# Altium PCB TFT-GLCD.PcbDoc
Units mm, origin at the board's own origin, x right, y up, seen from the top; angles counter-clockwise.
Board outline 98 x 57 mm, 2 copper layers (Top Layer, Bottom Layer), stack 1.571 mm thick; 54 components, 70 nets, 295 pads, 47 vias.
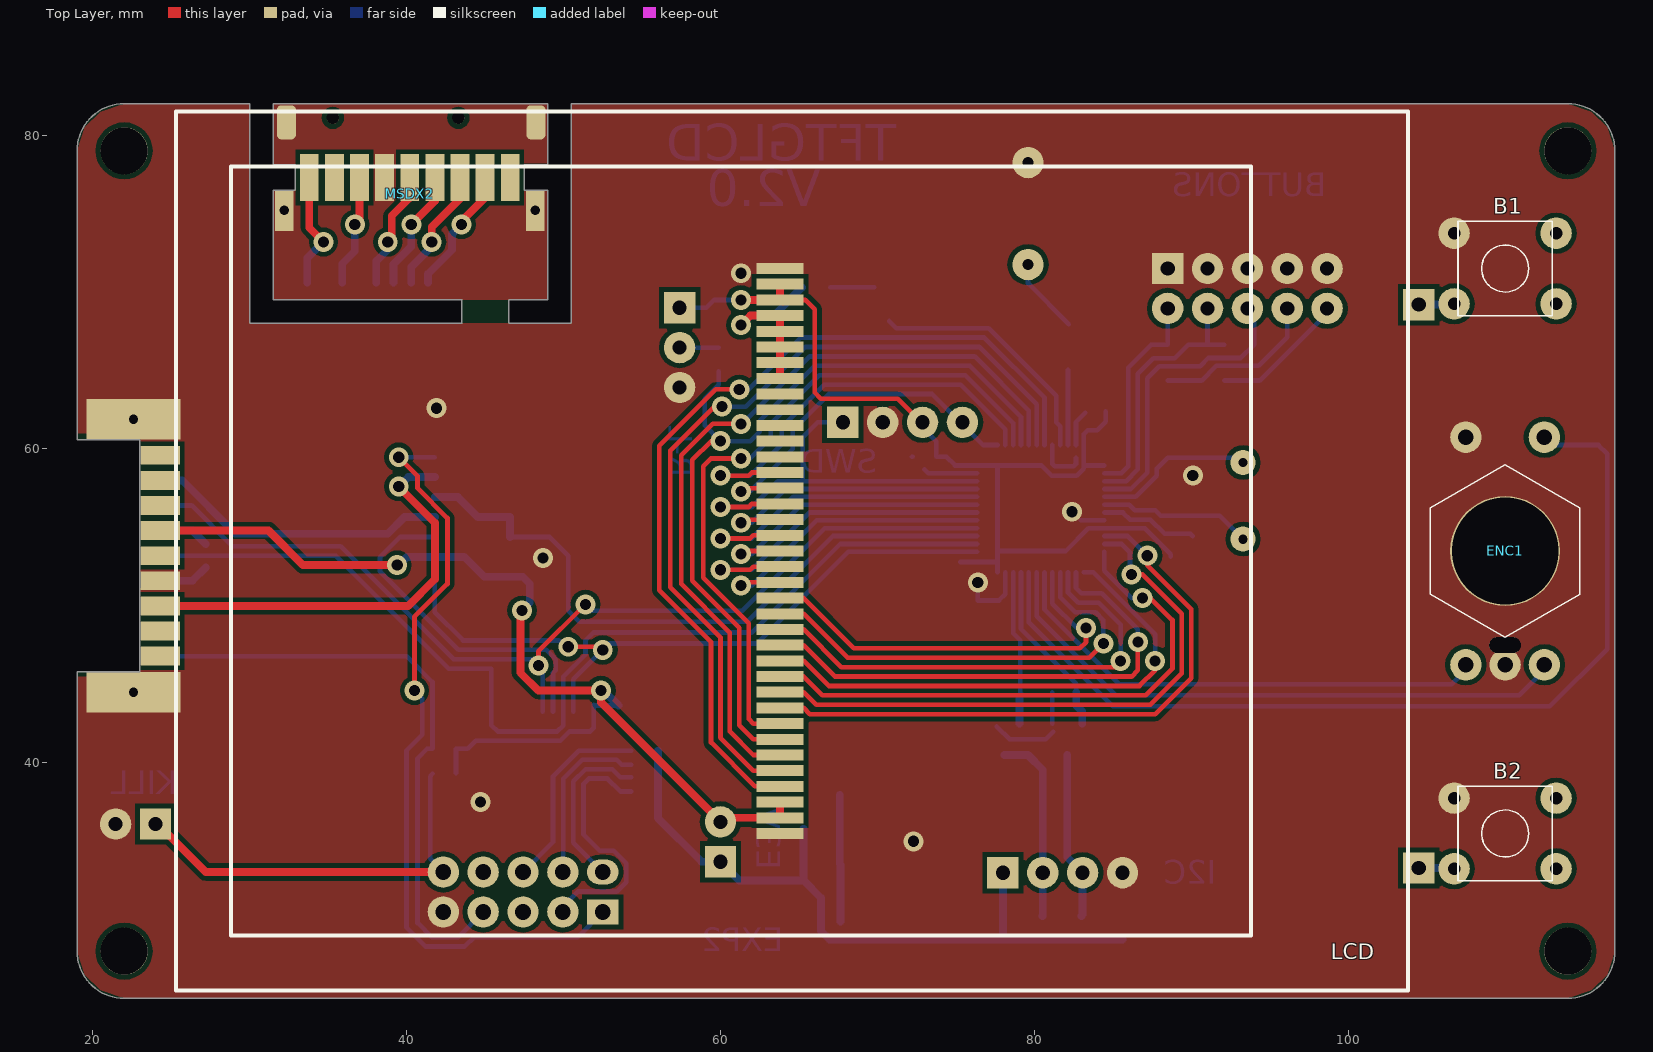
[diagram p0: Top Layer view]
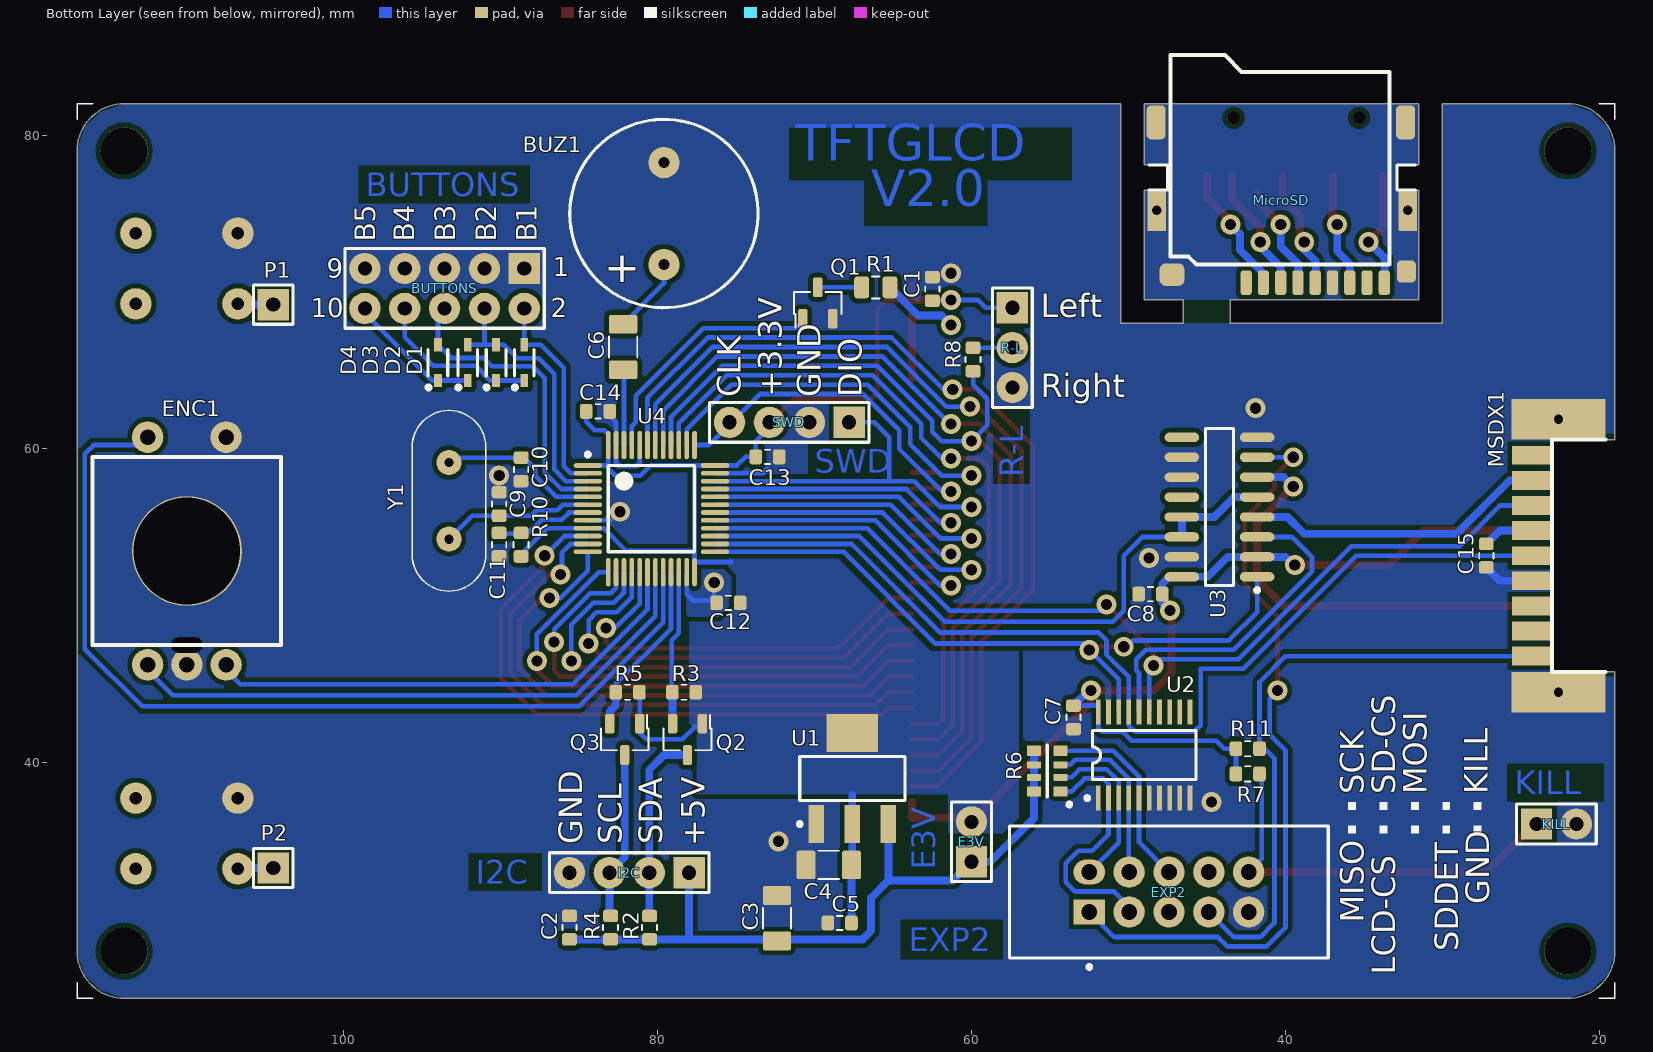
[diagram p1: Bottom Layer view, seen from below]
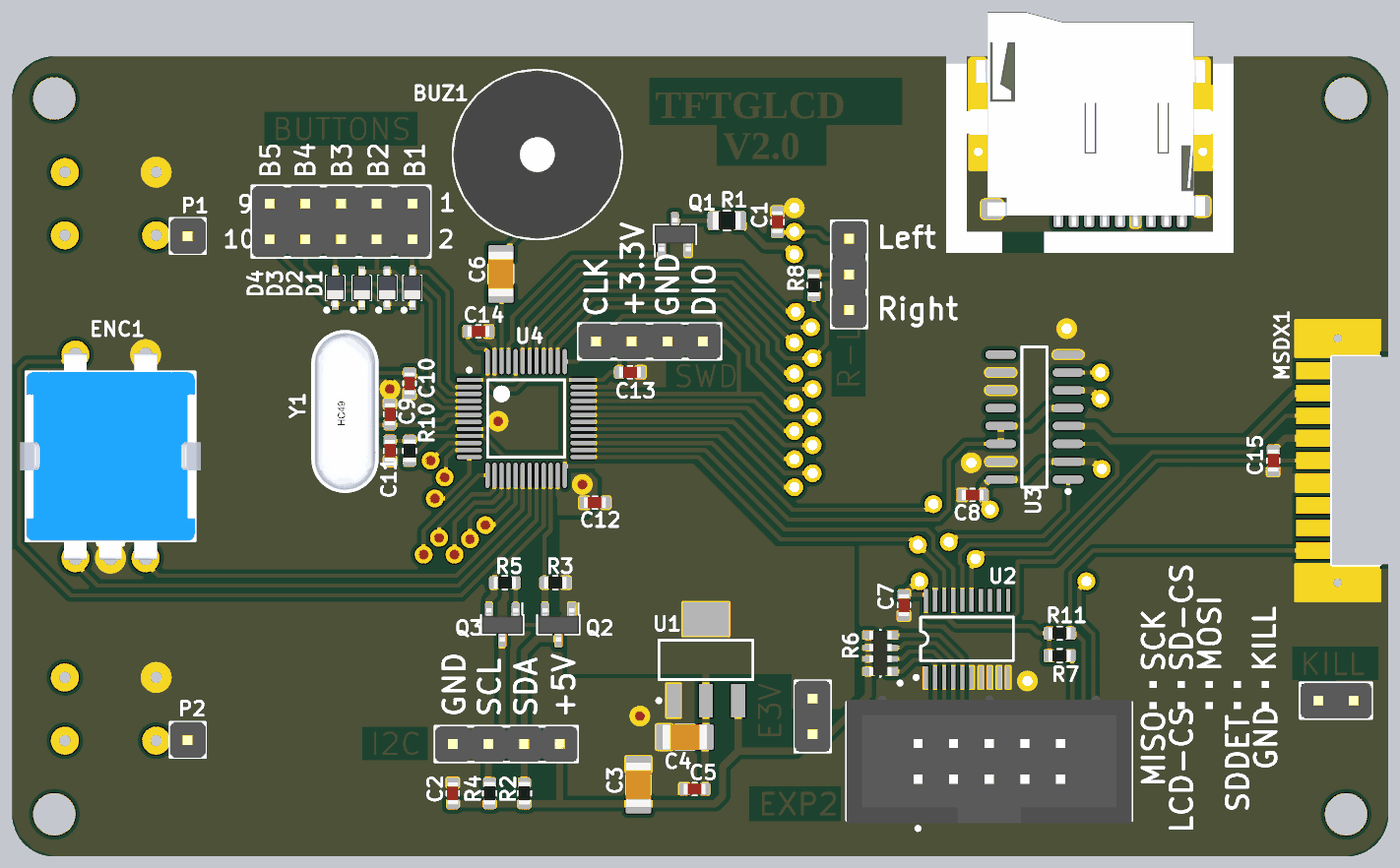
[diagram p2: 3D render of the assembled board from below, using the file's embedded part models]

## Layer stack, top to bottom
Top Solder: solder mask 0.0102, Solder Resist, Dk 3.5
Top Layer: signal copper 0.0356
Dielectric1: core 1.5, FR-4, Dk 4.8
Bottom Layer: signal copper 0.0356
Bottom Solder: solder mask 0.0102, Solder Resist, Dk 3.5

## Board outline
19,28 19,45.8 23,45.8 23,60.6 19,60.6 19,79 cw(c22,79) 22,82 30,82 30,68 43.5,68 43.5,69.5 31.5,69.5 31.5,76.5 32.9,76.5 32.9,78.1 31.5,78.1 31.5,82 49,82 49,78.1 47.5,78.1 47.5,76.5 49,76.5 49,69.5 46.5,69.5 46.5,68 50.5,68 50.5,82 114,82 cw(c114,79) 117,79 117,28 cw(c114,28) 114,25 22,25 cw(c22,28)

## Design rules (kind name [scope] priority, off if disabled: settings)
Clearance Clearance_1 [InPolygon] p1: gap=0.3 ignorepadtopadclearanceinfootprint=FALSE except(0: Arc-Hole Track-Hole SMDPad-Hole THPad-Hole Via-Hole Fill-Hole Poly-Hole Region-Hole Text-Hole)
Clearance [All] p2: gap=0.2 ignorepadtopadclearanceinfootprint=FALSE except(0: Arc-Hole Track-Hole SMDPad-Hole THPad-Hole Via-Hole Fill-Hole Poly-Hole Region-Hole Text-Hole)
ComponentClearance [All] p1 off: gap=0.254 collisioncheckmode=3 verticalgap=0.254 showdistances=FALSE
FabricationTestPointUsage [All] p1 off: valid=0 allowmultiple=FALSE
FabricationTestpoint [All] p1 off: side=3 testpointundercomponent=TRUE minsize=1.016 maxsize=2.54 preferedsize=1.524 minholesize=0 maxholesize=1.016 preferedholesize=0.813 testpointgrid=0.025 allowsidetop=TRUE allowsidebottom=TRUE usegrid=TRUE gridtolerance=0
FanoutControl Fanout_BGA [IsBGA] p1 off: bgadir=Out bgaviamode=Centered fanoutstyle=Auto fanoutdirection=Alternating viagrid=0.025 // Fanout_BGA (Default Rule)
FanoutControl Fanout_LCC [IsLCC] p2 off: bgadir=Out bgaviamode=Centered fanoutstyle=Auto fanoutdirection=Alternating viagrid=0.025 // Fanout_LCC (Default Rule)
FanoutControl Fanout_SOIC [IsSOIC] p3 off: bgadir=Out bgaviamode=Centered fanoutstyle=Auto fanoutdirection=Alternating viagrid=0.025 // Fanout_SOIC (Default Rule)
FanoutControl Fanout_Small [(CompPinCount < 5)] p4 off: bgadir=Out bgaviamode=Centered fanoutstyle=Auto fanoutdirection=OutThenIn viagrid=0.025 // Fanout_Small (Default Rule)
FanoutControl Fanout_Default [All] p5 off: bgadir=Out bgaviamode=Centered fanoutstyle=Auto fanoutdirection=Alternating viagrid=0.025 // Fanout_Default (Default Rule)
PolygonConnect [All] p1: connectstyle=Relief reliefconductorwidth=0.5 reliefentries=4 polygonreliefangle="90 Angle" airgapwidth=-0.1
RoutingVias [All] p1: holewidth=0.711 width=1.27 viastyle="Through Hole" minholewidth=0.711 minwidth=1.27 maxholewidth=0.711 maxwidth=1.27
SilkToSilkClearance [All] p1 off: silktosilkclearance=0.254
SilkToSolderMaskClearance SilkscreenOverComponentPads [IsPad] p1 off: minsilkscreentomaskgap=0.254 clearancetoexposedcopper=TRUE
SolderMaskExpansion [All] p1: expansion=0.1
Width [All] p1: maxlimit=2 minlimit=0.2 preferedwidth=0.3
20 further rules are at their usual default settings.

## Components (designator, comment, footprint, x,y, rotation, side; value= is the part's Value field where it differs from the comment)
B1 "SWT-2-x" SWT-2-x 110,71.5 r0 top
B2 "SWT-2-x" SWT-2-x 110,35.5 r0 top
BUTTONS "Header 5X2" HDR2X5 88.5,71.5 r0 bottom
BUZ1 "Buzer 1205" Buzer_12xx 79.6,75 r90 bottom
C1 "Cap" C0603_Samsung 62.5,70.2 r270 bottom value=100nF
C2 "Cap" C0603_Samsung 85.62,29.5 r270 bottom value=100nF
C3 "Cap" C1206_Murata 72.4,30.1 r270 bottom value=22uF
C4 "Cap" C1206_Murata 69.1,33.5 r180 bottom value=22uF
C5 "Cap" C0603_Samsung 68.4,29.8 r180 bottom value=100nF
C6 "Cap" C1206_Murata 82.2,66.5 r270 bottom value=4.7uF
C7 "Cap" C0603_Samsung 53.5,42.9 r90 bottom value=100nF
C8 "Cap" C0603_Samsung 48.6,50.75 r180 bottom value=100nF
C9 "Cap" C0603_Samsung 90.1,56.5 r270 bottom value=22pF
C10 "Cap" C0603_Samsung 88.7,58.7 r90 bottom value=22pF
C11 "Cap" C0603_Samsung 90.1,53.9 r90 bottom value=100nF
C12 "Cap" C0603_Samsung 75.5,50.2 r180 bottom value=100nF
C13 "Cap" C0603_Samsung 73,59.5 r0 bottom value=100nF
C14 "Cap" C0603_Samsung 83.8,62.4 r0 bottom value=100nF
C15 "Cap" C0603_Samsung 27.2,53.2 r90 bottom value=100nF
D1 "D_Schottky" SOD323FL_NXP 88.5,65.5 r90 bottom
D2 "D_Schottky" SOD323FL_NXP 90.3,65.5 r90 bottom
D3 "D_Schottky" SOD323FL_NXP 92.1,65.5 r90 bottom
D4 "D_Schottky" SOD323FL_NXP 94,65.5 r90 bottom
E3V "Header 2" HDR1X2 60,33.7 r90 bottom
ENC1 "Encoder EC-11" Encoder_bot 110,53.5 r0 top
EXP2 "HEADER 2X5_BH10" BH-10 52.5,30.5 r180 bottom
I2C "Header 4" HDR1X4 78,33 r0 bottom
KILL "Header 2" HDR1X2 24,36.1 r180 bottom
LCD "ILI9325" LCD_ILI9325-37pin 63.8,35.5 r0 top
MicroSD "Micro SD" TFP09-2-12B 42.5,70.6 r180 bottom
MSDX1 "CrossPCB-MicroSD" CrossPCB-MicroSD-MB 24.3,59.6 r270 bottom locked
MSDX2 "CrossPCB-MicroSD" CrossPCB-MicroSD-SD 46.6,77.3 r180 bottom
P1 "Plug" PLS-1x1 104.5,69.2 r180 bottom
P2 "Plug" PLS-1x1 104.5,33.3 r180 bottom
Q1 "IRLML6344" SOT23-3_IR 69.8,69.3 r90 bottom
Q2 "IRLML6344" SOT23-3_IR 78.1,41.5 r270 bottom
Q3 "IRLML6344" SOT23-3_IR 82.1,41.5 r270 bottom
R1 "R" R0805_UniOhm 66.1,70.3 r0 bottom value=33
R2 "R" R0603_UniOhm 80.52,29.5 r270 bottom value=10k
R3 "R" R0603_UniOhm 78.32,44.5 r180 bottom value=10k
R4 "R" R0603_UniOhm 83,29.5 r270 bottom value=10k
R5 "R" R0603_UniOhm 81.92,44.5 r180 bottom value=10k
R6 "array_r_x4s" RES_Array_ROHM_MNR14 55.172,39.476 r0 bottom value=10k
R7 "R" R0603_UniOhm 42.4,39.3 r180 bottom value=10k
R8 "R" R0603_UniOhm 59.9,65.7 r90 bottom value=10k
R10 "R" R0603_UniOhm 88.7,53.9 r90 bottom value=10k
R11 "R" R0603_UniOhm 42.4,40.9 r0 bottom value=10k
R-L "Header 3" HDR1X3 57.4,69 r270 bottom
SWD "Header 4" HDR1X4 67.8,61.7 r0 bottom
U1 "LM1117IMP-3.3" MP04A_N 67.6,39 r90 bottom
U2 "LCX541" TSSOP20 49,40.5 r180 bottom
U3 "74HC157" SO16_N 44.2,56.3 r0 bottom
U4 "STM32F103C8T6" LQFP48_N 80.4,56.2 r180 bottom
Y1 "XTAL" XTAL_HC-49_SS3 93.3,56.7 r90 bottom value=8MHz

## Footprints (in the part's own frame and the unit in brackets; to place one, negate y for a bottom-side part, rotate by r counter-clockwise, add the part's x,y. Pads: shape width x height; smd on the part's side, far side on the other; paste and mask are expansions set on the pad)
BH-10 [mm] "Shrouded Header,vertical,2.54mm pitch;1.00mm lead width,10 pins,2 rows,5 pins per row,20.30mm L X 8.40mm W X 9.30mm H body"
  rect 2x1.6 hole 1: 1(0,0)
  oval 2x1.6 hole 1: 2(0,2.54)
  round 2 hole 1: 3(2.54,0) 4(2.54,2.54) 5(5.08,0) 6(5.08,2.54) 7(7.62,0) 8(7.62,2.54) 9(10.16,0) 10(10.16,2.54)
  silkscreen extent -5.07,-3.63 15.23,5.47, body extent -5.07,-3.13 15.23,5.97, height 9.3
Buzer_12xx [mm]
  round 2 hole 0.7: 1(-3.25,0) 2(3.25,0)
  silkscreen extent -6,-6 6,6, body extent -5.95,-5.99 6,5.99, height 9.5
C0603_Samsung [mm] "Capacitor, Chip; 1.60 mm L X 0.80 mm W X 0.90 mm H body"
  rrect40% 0.8x0.95 smd paste-0.025 mask+0.05: 1(-0.75,0) 2(0.75,0)
  silkscreen extent -0.17,-0.45 0.17,0.45, body extent -0.8,-0.4 0.8,0.4, height 0.9
C1206_Murata [mm] "Capacitor, Chip; 3.20 mm L X 1.60 mm W X 1.80 mm H body"
  rrect20% 1.2x1.8 smd: 1(-1.45,0) 2(1.45,0)
  silkscreen extent -0.67,-0.9 0.67,0.9, body extent -1.6,-0.9 1.6,0.9, height 1.6
CrossPCB-MicroSD-MB [mm] "MicroSD CrossPCB connector MB side"
  rect 1.2x2.5 all layers, no hole: 1(0,0) 2(1.6,0) 3(3.2,0) 4(4.8,0) 5(6.4,0) 6(8,0) 7(9.6,0) 8(11.2,0) 9(12.8,0)
  rect 2.6x6 hole 0.6: 10(-2.3,1.7) 10(15.1,1.7)
  silkscreen extent -1,1.3 13.8,4.7
CrossPCB-MicroSD-SD [mm] "MicroSD CrossPCB connector SD side"
  rect 1.2x3 smd far side: 1(0,0) 2(1.6,0) 3(3.2,0) 4(4.8,0) 5(6.4,0) 6(8,0) 7(9.6,0) 8(11.2,0) 9(12.8,0)
  rect 1.2x2.6 hole 0.6: 10(-1.6,-2.1) 10(14.4,-2.1)
  silkscreen extent -2.1,-0.8 14.9,0.8
Encoder_bot [mm]
  oval 2x1 hole 1 slot 2 at 0 deg: 0(0,-6)
  round 7 hole 6.8: 0(0,0)
  round 2 hole 1: 1(-2.5,-7.25) 2(0,-7.25) 3(2.5,-7.25) 4(-2.5,7.25) 5(2.5,7.25)
  silkscreen extent -4.76,-5.5 4.76,5.5, body extent -6.43,-7.35 6.43,7.35, height 13.5
HDR1X2 [mm] "Connector; Header; 2 Position"
  rect 2x2 hole 0.9: 1(0,0)
  round 2 hole 0.9: 2(2.54,0)
  silkscreen extent -1.27,-1.27 3.81,1.27, body extent -1.25,-1.27 3.83,1.27, height 9
HDR1X3 [mm] "Connector; Header; 3 Position"
  rect 2x2 hole 0.9: 1(0,0)
  round 2 hole 0.9: 2(2.54,0) 3(5.08,0)
  silkscreen extent -1.27,-1.27 6.35,1.27, body extent -1.27,-1.27 6.35,1.27, height 9
HDR1X4 [mm] "Connector; Header; 4 Position"
  rect 2x2 hole 0.9: 1(0,0)
  round 2 hole 0.9: 2(2.54,0) 3(5.08,0) 4(7.62,0)
  silkscreen extent -1.27,-1.27 8.89,1.27, body extent -1.27,-1.27 8.89,1.27, height 9
HDR2X5 [mm] "Connector; Header; 5x2 Position"
  rect 2x2 hole 0.9: 1(0,0)
  round 2 hole 0.9: 2(0,2.54) 3(2.54,0) 4(2.54,2.54) 5(5.08,0) 6(5.08,2.54) 7(7.62,0) 8(7.62,2.54) 9(10.16,0) 10(10.16,2.54)
  silkscreen extent -1.27,-1.27 11.43,3.81, body extent -1.27,-1.27 11.43,3.81, height 9
LCD_ILI9325-37pin [mm]
  rect 3x0.7 smd: 1(0,0) 2(0,1) 3(0,2) 4(0,3) 5(0,4) 6(0,5) 7(0,6) 8(0,7) 9(0,8) 10(0,9) 11(0,10) 12(0,11) 13(0,12) 14(0,13) 15(0,14) 16(0,15) 17(0,16) 18(0,17) 19(0,18) 20(0,19) 21(0,20) 22(0,21) 23(0,22) 24(0,23) 25(0,24) 26(0,25) 27(0,26) 28(0,27) 29(0,28) 30(0,29) 31(0,30) 32(0,31) 33(0,32) 34(0,33) 35(0,34) 36(0,35) 37(0,36)
  silkscreen extent -38.5,-10 40,46, body extent -38.5,-10 40.1,46, height 3
LQFP48_N [mm] "Thin QFP, 48-Leads, Body 7x7mm, Pitch 0.5mm, IPC Medium Density"
  oval 1.8x0.3 smd: 1(-4.05,2.75) 2(-4.05,2.25) 3(-4.05,1.75) 4(-4.05,1.25) 5(-4.05,0.75) 6(-4.05,0.25) 7(-4.05,-0.25) 8(-4.05,-0.75) 9(-4.05,-1.25) 10(-4.05,-1.75) 11(-4.05,-2.25) 12(-4.05,-2.75) 25(4.05,-2.75) 26(4.05,-2.25) 27(4.05,-1.75) 28(4.05,-1.25) 29(4.05,-0.75) 30(4.05,-0.25) 31(4.05,0.25) 32(4.05,0.75) 33(4.05,1.25) 34(4.05,1.75) 35(4.05,2.25) 36(4.05,2.75)
  oval 0.3x1.8 smd: 13(-2.75,-4.05) 14(-2.25,-4.05) 15(-1.75,-4.05) 16(-1.25,-4.05) 17(-0.75,-4.05) 18(-0.25,-4.05) 19(0.25,-4.05) 20(0.75,-4.05) 21(1.25,-4.05) 22(1.75,-4.05) 23(2.25,-4.05) 24(2.75,-4.05) 37(2.75,4.05) 38(2.25,4.05) 39(1.75,4.05) 40(1.25,4.05) 41(0.75,4.05) 42(0.25,4.05) 43(-0.25,4.05) 44(-0.75,4.05) 45(-1.25,4.05) 46(-1.75,4.05) 47(-2.25,4.05) 48(-2.75,4.05)
  silkscreen extent -4.18,-2.75 2.75,3.57, body extent -3.5,-3.5 3.5,3.5, height 1.6
MP04A_N [mm] "SOT223, 4-Leads, Body 6.5x3.5mm, Pitch 2.3mm, Lead Span 7mm, IPC Medium Density"
  rect 2.4x1 smd: 1(-2.9,2.3) 2(-2.9,0) 3(-2.9,-2.3)
  rect 2.4x3.3 smd: 4(2.9,0)
  silkscreen extent -3.02,-3.35 1.4,3.48, body extent -1.85,-3.35 1.85,3.35, height 1.8
PLS-1x1 [mm]
  rect 2x2 hole 0.9: 1(0,0)
  silkscreen extent -1.25,-1.25 1.25,1.25, body extent -1.27,-1.27 1.27,1.27, height 9
R0603_UniOhm [mm] "Resistor, Chip; 1.60 mm L X 0.825 mm W X 0.55 mm H body"
  rrect40% 0.8x0.95 smd paste-0.025 mask+0.05: 1(-0.75,0) 2(0.75,0)
  silkscreen extent -0.17,-0.48 0.17,0.48, body extent -0.8,-0.41 0.8,0.41, height 0.55
R0805_UniOhm [mm] "Resistor, Chip; 2.00 mm L X 1.275 mm W X 0.65 mm H body"
  rrect40% 0.95x1.4 smd paste-0.025 mask+0.05: 1(-0.9,0) 2(0.9,0)
  silkscreen extent -0.25,-0.7 0.25,0.7, body extent -1,-0.64 1,0.64, height 0.65
RES_Array_ROHM_MNR14 [mm] "Resistor,Chip Array,0.80mm pitch;8 pin,1.60mm W X 3.20mm L X 0.60mm H, Convex"
  rrect15% 0.9x0.65 smd paste-0.025 mask+0.05: 1(-0.85,1.3) 4(-0.85,-1.3) 5(0.85,-1.3) 8(0.85,1.3)
  rrect22% 0.9x0.45 smd paste-0.025 mask+0.05: 2(-0.85,0.4) 3(-0.85,-0.4) 6(0.85,-0.4) 7(0.85,0.4)
  silkscreen extent -1.52,-1.65 0,2.25, body extent -0.8,-1.6 0.8,1.6, height 0.55
SO16_N [mm] "SOIC, 16-Leads, Body 9.9x3.9mm, Pitch 1.27mm, IPC Medium Density"
  oval 2.2x0.6 smd: 1(-2.4,4.445) 2(-2.4,3.175) 3(-2.4,1.905) 4(-2.4,0.635) 5(-2.4,-0.635) 6(-2.4,-1.905) 7(-2.4,-3.175) 8(-2.4,-4.445) 9(2.4,-4.445) 10(2.4,-3.175) 11(2.4,-1.905) 12(2.4,-0.635) 13(2.4,0.635) 14(2.4,1.905) 15(2.4,3.175) 16(2.4,4.445)
  silkscreen extent -2.52,-5 0.9,5.42, body extent -1.95,-4.95 1.95,4.95, height 1.75
SOD323FL_NXP [mm] "SODFL Diode;1.80mm W X 1.35mm L X 0.80mm H body"
  rrect10% 0.85x0.5 smd paste-0.025 mask+0.05: A(1.14,0) C(-1.14,0)
  silkscreen extent -1.7,-0.63 0.85,0.73, body extent -1.35,-0.67 1.35,0.68, height 0.79
SOT23-3_IR [mm] "Small Outline Transistor (SOT23), 0.95 mm pitch; 3 pin, 2.92 mm L X 1.30 mm W X 1.12 mm H body"
  rrect40% 1.25x0.6 smd paste-0.025 mask+0.05: 1(-1,0.95) 2(-1,-0.95) 3(1,0)
  silkscreen extent -1.57,-1.52 0.7,1.52, body extent -1.18,-1.46 1.18,1.46, height 1.12
SWT-2-x [mm] "Button"
  round 2 hole 0.8: 1(-3.25,2.25) 2(-3.25,-2.25) 3(3.25,-2.25) 4(3.25,2.25)
  silkscreen extent -3,-3 3,3
TFP09-2-12B [mil] "http://ali.pub/2rgdx8"
  round 30 hole 31.5 mask+0: 0(-31.5,413.39) 0(283.46,413.39)
  rrect50% 28x62 smd: 1(0,0) 2(43.31,0) 3(86.61,0) 4(129.92,0) 5(173.23,0) 6(216.54,0) 7(259.84,0) 8(303.15,0) 9(346.46,0)
  rrect50% 48x56 smd: 10(402,28)
  rrect50% 62x56 smd: 11(-186,20)
  rrect50% 48x86 all layers, no hole: 12(-226,402) 12(400,402)
  silkscreen extent -190,45 360,571, body extent -230,-27 412,572, height 79
TSSOP20 [mm] "Shrink Small Outline; 20 Leads; Body Width 4.4 mm; Pitch 0.65 mm"
  rect 0.3x1.6 smd: 1(-2.925,-2.75) 2(-2.275,-2.75) 3(-1.625,-2.75) 4(-0.975,-2.75) 5(-0.325,-2.75) 6(0.325,-2.75) 7(0.975,-2.75) 8(1.625,-2.75) 9(2.275,-2.75) 10(2.925,-2.75) 11(2.925,2.75) 12(2.275,2.75) 13(1.625,2.75) 14(0.975,2.75) 15(0.325,2.75) 16(-0.325,2.75) 17(-0.975,2.75) 18(-1.625,2.75) 19(-2.275,2.75) 20(-2.925,2.75)
  silkscreen extent -3.75,-2.87 3.3,1.55
XTAL_HC-49_SS3 [mm] "Quartz"
  round 1.6 hole 0.6: 1(-2.438,0) 2(2.438,0)
  silkscreen extent -5.76,-2.35 5.76,2.35, body extent -5.75,-2.32 5.75,2.33, height 3.5

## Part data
BUTTONS: "Header, 5-Pin, Dual row"
BUZ1: library part Buzer
C1 C2 C5 C7 C8 C11 C12 C13 C14 C15: library part CL10B104KB8NNNC, Manufacturer="Samsung Electro-Mechanics", PartName=CL10, Tolerance="10 %", Voltage=50V
C3 C4 C6: library part GRM31CR71H475KA12L, Manufacturer=muRata, PartName=GRM31, Tolerance="10 %", Voltage=50V
C9 C10: library part CL10C220JB8NNNC, Manufacturer="Samsung Electro-Mechanics", PartName=CL10, Tolerance="5 %", Voltage=50V
D1 D2 D3 D4: library part PMEG6010CEJ,115, "60V, 1A, very low VF MEGA Schottky barrier rectifiers", Manufacturer="NXP Semiconductors", PartName=PMEG6010CEJ
E3V KILL: "Header, 2-Pin"
ENC1: library part Encoder, "Rotary Encoder with button"
EXP2: library part BH-10, "IDC-10M Connector (BH-10)", Manufacturer=Unknown, PartName=BH-10V
I2C SWD: "Header, 4-Pin"
LCD: library part LCD_ILI9325-37pin
MicroSD: library part TFP09-2-12B
MSDX1 MSDX2: "Micro SD CrossPCB connector"
Q1 Q2 Q3: library part IRLML6344TRPBF, "30 V, 5.0 A, 0.029 Ohm Single N-Channel HEXFET Power MOSFET", Manufacturer="International Rectifier"
R1: library part 0805S8F4700T50, Manufacturer=uniOhm, PartName=0805S, TempCo="100 ppm", Tolerance="1 %"
R2 R3 R4 R5 R7 R8 R10 R11: library part 0603SAF1002T50, Manufacturer=uniOhm, PartName=0603SA, TempCo="100 ppm", Tolerance="1 %"
R6: library part MNR14ERAPJ103, "4x Chip Array Convex", Manufacturer=ROHM, PartName=MNR14, TempCo="200 ppm", Tolerance="5 %"
R-L: "Header, 3-Pin"
U1: "800mA Low-Dropout Linear Regulator", DigiKeyPartNumber=LM1117IMP-3.3CT-ND, Manufacturer="National Semiconductor", PackageTopMarking=XYTT*N05B, PowerWise=N
U2: library part 74LCX541MTC, "Low Voltage Octal Buffer with 5V Tolerant Inputs and Outputs", Manufacturer="Fairchild Semiconductor", PartName=LVC541PW
U3: library part 74LVQ157M, "Low-Voltage Quad 2-Channel Multiplexer"
U4: "STM32 ARM-based 32-bit MCU with 64 Kbytes Flash, 48-pin LQFP, Industrial Temperature"
Y1: library part "KX-3HT 10.0MHZ", "10MHz Quartz HC49", Manufacturer="GEYER ELECTRONIC", PartName=KX-3HT

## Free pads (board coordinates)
  round 3 hole 3: 1(22,28) 1(22,79) 1(114,28) 1(114,79)

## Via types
v1: diameter 1.27, hole 0.711, Top Layer to Bottom Layer, 47 vias

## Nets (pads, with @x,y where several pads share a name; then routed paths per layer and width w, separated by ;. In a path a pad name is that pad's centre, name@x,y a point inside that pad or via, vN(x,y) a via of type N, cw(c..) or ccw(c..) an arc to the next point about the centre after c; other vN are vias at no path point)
+3.3V: C1.2 C4.2 C5.2 C7.2 C8.2 C12.2 C13.2 C14.2 C15.2 E3V.2 LCD.2 LCD.3 LCD.35 LCD.36 MSDX1.4 Q2.1 Q3.1 R3.2 R5.2 R7.1 R10.1 R11.2 R-L.1 SWD.3 U1.2 U1.4 U2.20 U3.2 U3.16 U4.1 U4.9 U4.24 U4.36 U4.48 | length 150.6
  Top Layer w0.3: LCD.35@64,69.3 64.2,69.5 65.4,69.5 66,68.9 66,63.6 66.4,63.2 71.3,63.2 SWD.3@72.79,61.71
  Top Layer w0.5: MSDX1.4 31.2,54.8 33.4,52.6 v1(39.4,52.6) ; v1(47.359,49.716) 47.25,49.607 47.25,45.75 48.4,44.6 v1(52.384,44.6) 52.384,43.856 E3V.2 60.26,36.5 LCD.2 LCD.3 ; v1(61.3,69.5) LCD.35 LCD.36
  Bottom Layer w0.3: R7.1@43.15,39.35 R11.2 43.9,40.9 44.4,41.4 49.8,41.4 50.4,42 51.7,42 51.925,42.225 U2.20 51.925,43.7 51.975,43.65 C7.2 ; R-L.1 59.1,69 59.6,69.5 v1(61.3,69.5) ; v1@61.25,69.45 C1.2 C1.2@62.45,69.4 ; SWD.3@72.54,61.7 73.75,60.49 C13.2 74.4,59.5 74.95,58.95 U4.36 77.65,58.95 ; 75.3,52.8 U4.24@77.65,52.8 ; 77.61,42.31 78.42,41.5 80.72,41.5 Q3.1@81.2,41.98 ; U4.24 U4.24@77.65,52.8 ; Q3.1 R5.2@81.15,44.48 ; U4.1 83.15,58.95 ; C14.2 84.55,61.75 84,61.2 83.4,61.2 83.15,60.95 U4.48 83.15,58.95 ; R10.1 88.7,53.3 87.05,54.95 U4.9 83.45,54.95 82,53.5 77.65,53.5 ; U4.24@77.65,52.8 77.65,53.5 ; 77.65,53.5 77.65,58.95 ; 77.65,58.95 80.45,58.95 81.1,58.3 82.7,58.3 83.15,58.75 83.15,58.95
  Bottom Layer w0.5: MSDX1.4 26.35,54.8 C15.2 ; v1(39.4,52.6) 39.5,52.6 40.025,53.125 U3.2 43.675,53.125 44.945,51.855 U3.16 47.4,51.855 47.85,51.405 C8.2 47.85,50.207 v1(47.359,49.716) ; v1(52.384,44.6) 52.55,44.6 C7.2 ; C4.2@67.6,33.55 U1.2 67.6,37.95 ; C5.2@67.65,29.9 C4.2
+5V: C2.2 C3.2 E3V.1 I2C.1 R2.2 R4.2 R6.5 R6.6 R6.7 R6.8 U1.3 | length 45.9
  Bottom Layer w0.5: R6.5 R6.6 R6.7 R6.8 56.022,36.478 58.8,33.7 E3V.1 61.2,32.5 65.3,32.5 ; U1.3@65.3,35.8 65.3,32.5 ; I2C.1 78,28.75 ; C2.2 R2.2 78,28.75 ; 65.3,32.5 66.4,31.4 66.4,29.3 66.95,28.75 78,28.75
B1: BUTTONS.2 D1.A U4.2 | length 13.5
  Bottom Layer w0.3: U4.2 85.55,58.45 85.99,58.89 85.99,65.19 87.44,66.64 D1.A BUTTONS.2
B2: BUTTONS.4 D2.A D3.A U4.3 | length 17.1
  Bottom Layer w0.3: U4.3 85.85,57.95 86.6,58.7 86.6,64.8 87.576,65.776 88.957,65.776 89.821,66.64 D2.A D3.A ; 91.04,66.68 BUTTONS.4
B3: BUTTONS.6 D4.A U4.4 | length 19.4
  Bottom Layer w0.3: U4.4 86.15,57.45 87.2,58.5 87.2,64.5 87.976,65.276 90.576,65.276 91.1,65.8 93.16,65.8 D4.A 94,68.54 BUTTONS.6
B4: BUTTONS.8 D1.C D2.C | length 10.6
  Bottom Layer w0.3: D1.C D2.C 90.66,64.36 91.6,65.3 94.3,65.3 96.12,67.12 BUTTONS.8
B5: BUTTONS.10 D3.C D4.C | length 8.3
  Bottom Layer w0.3: D3.C D4.C 94.36,64.36 BUTTONS.10@98.66,68.66
BEEP: C6.2 U4.46 | length 4.8
  Bottom Layer w0.3: U4.46 C6.2@82.15,65.05
BRIGHTNES: Q1.1 U4.45 | length 15.9
  Bottom Layer w0.3: Q1.1@70.75,68.15 71.2,67.7 77.1,67.7 81.4,63.4 81.4,61.7 81.65,61.45 U4.45
BTNEN2: EXP2.5
CS-: LCD.4 U4.43 | length 57.8
  Top Layer w0.3: v1(61.2,63.8) 59.7,63.8 56.1,60.2 56.1,51 59.4,47.7 59.4,41.3 62.2,38.5 LCD.4
  Bottom Layer w0.3: v1(61.2,63.8) 61.8,63.8 65.1,67.1 76.8,67.1 80.65,63.25 U4.43
CS-LCD: U2.18 U3.1 U4.25 | length 45.2
  Top Layer w0.3: v1(50.3,47.4) 52.3,47.4 v1(52.5,47.2)
  Bottom Layer w0.3: U3.1 41.8,49.6 43.6,47.8 49.7,47.8 50.1,47.4 v1@50.149,47.4 ; v1@50.1,47.449 v1@50.149,47.4 ; v1(50.3,47.4) v1@50.149,47.4 ; U2.18 50.625,45.325 v1(52.5,47.2) 52.9,47.6 62.3,47.6 68.15,53.45 U4.25
CS-SD: MSDX1.2 U3.4 | length 19.3
  Bottom Layer w0.5: MSDX1.2 25.7,58 29.1,54.6 38.8,54.6 39.865,55.665 U3.4
CS-SD-I: U2.16 U3.3 | length 21.9
  Bottom Layer w0.3: U3.3 39.595,54.395 38.3,53.1 38.3,52.2 43.3,47.2 48.9,47.2 49.5,46.6 49.5,45.9 49.325,45.725 U2.16
D0: LCD.9 U4.10 | length 39.9
  Top Layer w0.3: LCD.9 65.3,43.5 65.7,43.1 87.7,43.1 90,45.4 90,49.8 87.2,52.6 v1(87.2,53.2)
  Bottom Layer w0.3: U4.10 85.95,54.45 v1(87.2,53.2) v1@87.45,52.95
D1: LCD.10 U4.11 | length 38.2
  Top Layer w0.3: LCD.10 65.3,44.5 66.1,43.7 87.4,43.7 89.4,45.7 89.4,49.5 86.9,52 v1(86.2,52) v1@86.1,52
  Bottom Layer w0.3: U4.11 85.55,53.95 86.1,53.4 v1@86.1,52
D2: LCD.11 U4.12 | length 36.2
  Top Layer w0.3: LCD.11 65.3,45.5 66.5,44.3 87.1,44.3 88.8,46 88.8,49.1 87.4,50.5 v1(86.9,50.5)
  Bottom Layer w0.3: U4.12 84.45,52.25 86.2,50.5 v1(86.9,50.5)
D3: LCD.12 U4.13 | length 33.5
  Top Layer w0.3: LCD.12 65.3,46.5 66.9,44.9 86.7,44.9 87.7,45.9 v1(87.7,46.5)
  Bottom Layer w0.3: U4.13 83.75,52.15 87.7,48.2 v1(87.7,46.5)
D4: LCD.13 U4.14 | length 32.4
  Top Layer w0.3: LCD.13 65.3,47.5 67.3,45.5 86.2,45.5 86.6,45.9 v1(86.6,47.7)
  Bottom Layer w0.3: U4.14 82.65,51.15 83,50.8 84.3,50.8 86.6,48.5 v1(86.6,47.7)
D5: LCD.14 U4.15 | length 30.7
  Top Layer w0.3: LCD.14 65.3,48.5 67.7,46.1 85.1,46.1 v1(85.5,46.5)
  Bottom Layer w0.3: U4.15 82.15,50.85 82.8,50.2 84.1,50.2 85.5,48.8 v1(85.5,46.5)
D6: LCD.15 U4.16 | length 28.6
  Top Layer w0.3: LCD.15 65.3,49.5 68.1,46.7 83.5,46.7 v1(84.4,47.6)
  Bottom Layer w0.3: U4.16 81.65,50.55 82.6,49.6 83.9,49.6 84.4,49.1 v1(84.4,47.6)
D7: LCD.16 U4.17 | length 27.1
  Top Layer w0.3: LCD.16 65.3,50.5 68.5,47.3 82.9,47.3 83.3,47.7 v1(83.3,48.6)
  Bottom Layer w0.3: U4.17 81.15,50.15 82.7,48.6 v1(83.3,48.6) ; v1@83.4,48.7 v1@83.7,48.4
D8: LCD.17 U4.29 | length 19.4
  Top Layer w0.3: v1(61.3,51.3) 61.5,51.5 LCD.17
  Bottom Layer w0.3: v1(61.3,51.3) 62,51.3 66.15,55.45 U4.29
D9: LCD.18 U4.30 | length 21.7
  Top Layer w0.3: v1(60,52.3) 61.9,52.3 62.1,52.5 LCD.18
  Bottom Layer w0.3: v1(60,52.3) 62,52.3 65.65,55.95 U4.30
D10: LCD.19 U4.31 | length 18.9
  Top Layer w0.3: v1(61.3,53.3) 61.5,53.5 LCD.19
  Bottom Layer w0.3: v1(61.3,53.3) 62,53.3 65.15,56.45 U4.31
D11: LCD.20 U4.32 | length 21.3
  Top Layer w0.3: v1(60,54.3) 61.9,54.3 62.1,54.5 LCD.20
  Bottom Layer w0.3: v1(60,54.3) 62,54.3 64.65,56.95 U4.32
D12: LCD.21 U4.33 | length 18.5
  Top Layer w0.3: v1(61.3,55.3) 61.5,55.5 LCD.21
  Bottom Layer w0.3: v1(61.3,55.3) 62,55.3 64.15,57.45 U4.33
D13: LCD.22 SWD.1 U4.34 | length 26.3
  Top Layer w0.3: v1(60,56.3) 61.8,56.3 62,56.5 LCD.22
  Bottom Layer w0.3: v1(60,56.3) 62,56.3 63.65,57.95 65.25,57.95 ; SWD.1@67.46,61.7 66.2,61.7 65.25,60.75 65.25,57.95 ; U4.34 65.25,57.95
D14: LCD.23 SWD.4 U4.37 | length 23.6
  Top Layer w0.3: v1(61.3,57.3) 61.5,57.5 LCD.23
  Bottom Layer w0.3: v1(61.3,57.3) 61.9,57.3 64.6,60 64.6,61.2 66.9,63.5 73.5,63.5 76.75,60.25 U4.37
D15: LCD.24 U4.38 | length 27.3
  Top Layer w0.3: v1(60,58.3) 61.8,58.3 62,58.5 LCD.24
  Bottom Layer w0.3: v1(60,58.3) 61.9,58.3 63.9,60.3 63.9,61.4 66.6,64.1 75.3,64.1 78.15,61.25 U4.38
ENCA: ENC1.1 U4.18 | length 31.9
  Bottom Layer w0.3: U4.18 80.65,49.75 85.4,45 106.6,45 107.5,45.9 ENC1.1
ENCB: ENC1.3 U4.19 | length 38.3
  Bottom Layer w0.3: U4.19 80.15,49.35 85.2,44.3 110.901,44.3 112.5,45.899 ENC1.3
ENCBT: ENC1.5 U4.20 | length 60
  Bottom Layer w0.3: U4.20 79.65,48.95 85,43.6 112.851,43.6 116.5,47.249 116.5,59.7 115.95,60.25 ENC1.5@113,60.25
GND: B1.1 B2.1 BUTTONS.1 BUTTONS.3 BUTTONS.5 BUTTONS.7 BUTTONS.9 BUZ1.2 C1.1 C2.1 C3.1 C4.1 C5.1 C7.1 C8.1 C9.1 C10.1 C11.1 C12.1 C13.1 C14.1 C15.1 ENC1.0 ENC1.2 ENC1.4 EXP2.9 I2C.4 KILL.2 LCD.1 LCD.25 LCD.37 MSDX1.6 MSDX1.10 Q1.2 R-L.3 SWD.2 U1.1 U2.1 U2.6 U2.7 U2.8 U2.9 U2.10 U2.19 U3.8 U3.10 U3.11 U3.15 U4.8 U4.23 U4.35 U4.44 U4.47 | length 18.7
  Bottom Layer w0.3: C13.1@72.2,59.5 C13.1 ; 73,58.7 73.25,58.45 U4.35 ; v1(76.4,51.5) 76.4,50.35 77.75,50.35 78.15,50.75 U4.23 ; U4.44 81.15,59.05 81.3,58.9 82.5,58.9 82.65,59.05 U4.47@82.65,59.45 ; U4.47 82.65,61.7 C14.1@83.25,62.3 ; 82.95,55.45 U4.8
  Bottom Layer w0.5: MSDX1.6@23.8,51.6 MSDX1.6 26.35,51.6 C15.1
  other v1: 72.3,35 44.7,37.5 48.7,53.045 82.4,56 90.1,58.3 41.9,62.6 61.3,71.2
I2CSCL: I2C.3 Q3.3 R4.1 | length 10.7
  Bottom Layer w0.5: Q3.3 82.1,33.98 I2C.3 83.08,30.33 R4.1
I2CSDA: I2C.2 Q2.3 R2.1 | length 12.1
  Bottom Layer w0.5: Q2.3 79.6,40.5 80.54,39.56 I2C.2 80.54,30.27 R2.1
KILL: EXP2.10 KILL.1 R7.2 | length 26.3
  Top Layer w0.5: KILL.1@24.1,36.1 24.14,36.1 27.2,33.04 EXP2.10
  Bottom Layer w0.3: R7.2 41.5,39.15 41.5,33.88 EXP2.10
  Bottom Layer w0.5: EXP2.10 EXP2.10@42.4,33.1
LCD-CS: EXP2.3 R6.1 U2.2 | length 16.5
  Bottom Layer w0.3: EXP2.3 49.96,30.86 50.9,31.8 53.4,31.8 54,32.4 54,33.6 53.2,34.4 52.3,34.4 51.275,35.425 U2.2 51.275,38.675 51.6,39 52.8,39 53.624,38.176 R6.1
MISO: EXP2.1 U3.7 | length 49
  Top Layer w0.3: v1(39.5,59.475) 40.7,58.275 40.7,57.5 42.6,55.6 42.6,51.4 40.5,49.3 v1(40.5,44.6)
  Bottom Layer w0.3: v1(39.5,59.475) U3.7 ; v1(40.5,44.6) 41,44.1 41,41.8 40,40.8 40,29.5 41.2,28.3 43.7,28.3 44.3,28.9 50.9,28.9 EXP2.1
MISO-L: U3.5 U3.13 U3.14 U4.27 | length 42.9
  Bottom Layer w0.3: U3.14 49.1,54.395 50.3,53.195 50.3,49.7 51,49 61.7,49 67.15,54.45 U4.27
  Bottom Layer w0.5: U3.5 43.265,56.935 44.535,55.665 U3.13 U3.14
MISO-SD: MSDX1.7 U3.6 | length 27.6
  Top Layer w0.5: MSDX1.7 40.1,50 41.8,51.7 41.8,55.3 v1(39.5,57.6)
  Bottom Layer w0.5: v1(39.5,57.6) 40.105,58.205 U3.6
MOSI: EXP2.6 R6.4 U2.5 | length 12.6
  Bottom Layer w0.3: EXP2.6 49.325,34.945 U2.5 49.325,39.125 50.976,40.776 R6.4
MOSI-I: MSDX1.3 U2.15 U4.28 | length 63.8
  Top Layer w0.3: v1(48.4,46.2) 48.4,47.1 v1(51.4,50.1)
  Bottom Layer w0.3: MSDX1.3 26.3,56.4 28.9,53.8 35.8,53.8 37.8,51.8 37.8,51.793 42.993,46.6 48,46.6 v1(48.4,46.2) 48.675,45.925 U2.15 ; v1(51.4,50.1) 51.8,49.7 61.4,49.7 66.65,54.95 U4.28
NetB1_2: B1.2 P1.1 | length 2.2
  Bottom Layer w0.5: P1.1 B1.2@106.7,69.2
NetB2_2: B2.2 P2.1 | length 2.2
  Bottom Layer w0.5: P2.1 B2.2@106.7,33.3
NetBUZ1_1: BUZ1.1 C6.1 | length 4.9
  Bottom Layer w0.3: BUZ1.1 79.6,70.55 C6.1
NetC9_2: C9.2 U4.6 Y1.1 | length 9.8
  Bottom Layer w0.3: U4.6 86.05,56.45 86.4,56.1 87.7,56.1 88.05,55.75 C9.2 91.812,55.75 Y1.1
NetC10_2: C10.2 U4.5 Y1.2 | length 10.3
  Bottom Layer w0.3: U4.5 86.45,56.95 87.8,58.3 87.8,58.751 88.499,59.45 C10.2 92.988,59.45 Y1.2
NetC11_2: C11.2 R10.2 U4.7 | length 6.3
  Bottom Layer w0.3: U4.7 85.65,55.95 86.1,55.5 87.4,55.5 88.3,54.6 89.95,54.6 C11.2@90.1,54.45
NetLCD_30: LCD.30 LCD.31 LCD.32 LCD.33 LCD.34 R1.1 | length 11.6
  Top Layer w0.5: v1(61.3,67.9) 61.9,68.5 LCD.34 LCD.33 LCD.32 LCD.31 LCD.30
  Bottom Layer w0.5: v1(61.3,67.9) 61.9,68.5 63.4,68.5 R1.1
NetMicroSD_2: MicroSD.2 MSDX2.2 | length 8.5
  Top Layer w0.5: v1(43.5,74.3) 43.3,74.3 45,76 MSDX2.2@45,77.4
  Bottom Layer w0.5: MicroSD.2@41.37,70.6 41.37,71.17 42.9,72.7 42.9,73.7 43.2,74 v1@43.2,74.3
NetMicroSD_3: MicroSD.3 MSDX2.3 | length 8.1
  Top Layer w0.5: v1(41.6,73.2) 41.6,74.15 43.4,75.95 MSDX2.3@43.4,77.4
  Bottom Layer w0.5: MicroSD.3 40.3,71.6 41.6,72.9 v1(41.6,73.2)
NetMicroSD_4: MicroSD.4 MSDX2.4 | length 6.8
  Top Layer w0.5: v1(40.3,74.3) 41.8,75.8 MSDX2.4@41.8,76.3
  Bottom Layer w0.5: MicroSD.4@39.17,70.6 39.17,71.77 40.3,72.9 v1(40.3,74.3)
NetMicroSD_5: MicroSD.5 MSDX2.5 | length 7.7
  Top Layer w0.5: v1(38.8,73.2) 39.056,73.456 39.056,74.856 40.2,76 MSDX2.5@40.2,77.4
  Bottom Layer w0.5: MicroSD.5@38.07,70.6 38.07,71.97 38.8,72.7 v1(38.8,73.2)
NetMicroSD_6: MicroSD.6 MicroSD.10 MicroSD.11 MicroSD.12 MSDX2.6 MSDX2.10
NetMicroSD_7: MicroSD.7 MSDX2.7 | length 7.3
  Top Layer w0.5: v1(36.7,74.3) 37,74.6 MSDX2.7@37,77.4
  Bottom Layer w0.5: MicroSD.7 35.9,71.8 36.7,72.6 v1(36.7,74.3)
NetMicroSD_9: MicroSD.9 MSDX2.9 | length 7.6
  Top Layer w0.5: MSDX2.9@33.8,77.4 33.8,74.1 v1(34.7,73.2)
  Bottom Layer w0.5: MicroSD.9@33.67,70.6 33.67,72.17 v1(34.7,73.2)
NetQ1_3: Q1.3 R1.2 | length 2.8
  Bottom Layer w0.3: R1.2 Q1.3
NetR8_2: R8.2 R-L.2 | length 2.5
  Bottom Layer w0.3: R-L.2 R8.2@59.89,66.46
RD-: LCD.7 R8.1 U4.40 | length 53.3
  Top Layer w0.3: v1(60,60.5) 59.4,60.5 58.2,59.3 58.2,51.6 61.2,48.6 61.2,42.4 62.1,41.5 LCD.7
  Bottom Layer w0.3: R8.1 59.9,64.1 59,63.2 59,61.5 v1(60,60.5) 61.9,60.5 62.5,61.1 62.5,61.8 66,65.3 75.9,65.3 79.15,62.05 U4.40
RESET: EXP2.8
RS-: LCD.5 U4.42 | length 54.5
  Top Layer w0.3: v1(60.1,62.7) 59.6,62.7 56.8,59.9 56.8,51.2 60,48 60,41.6 62.1,39.5 LCD.5
  Bottom Layer w0.3: v1(60.1,62.7) 61.6,62.7 65.4,66.5 76.5,66.5 80.15,62.85 U4.42
RST-: LCD.8 U4.39 | length 44.8
  Top Layer w0.3: v1(61.3,59.4) 59.4,59.4 58.9,58.9 58.9,51.8 61.8,48.9 61.8,42.8 62.1,42.5 LCD.8
  Bottom Layer w0.3: v1(61.3,59.4) 61.9,59.4 63.2,60.7 63.2,61.6 66.3,64.7 75.6,64.7 78.65,61.65 U4.39
SCK: EXP2.2 R6.2 U2.3 | length 10.8
  Bottom Layer w0.3: EXP2.2 50.625,34.915 U2.3 50.625,38.825 51.4,39.6 53.1,39.6 53.624,39.076 R6.2
SCK-I: MSDX1.5 U2.17 U4.26 | length 66.1
  Bottom Layer w0.3: MSDX1.5 35.5,53.2 42.7,46 45.4,46 45.4,42.4 45.8,42 49.6,42 49.975,42.375 U2.17 49.975,45.475 51.4,46.9 51.4,47.8 51.9,48.3 62,48.3 67.65,53.95 U4.26
SCL: Q3.2 R5.1 U4.21 | length 11.3
  Bottom Layer w0.3: U4.21 79.15,48.55 82.67,45.03 R5.1
  Bottom Layer w0.5: R5.1 82.67,43.65 83.05,43.27 Q3.2
SD-CS: EXP2.4 R6.3 U2.4 | length 10.9
  Bottom Layer w0.3: EXP2.4 49.975,33.055 U2.4 49.975,38.975 51.2,40.2 53.4,40.2 53.724,39.876 R6.3
SD-DET: EXP2.7 MSDX1.9 R11.1 | length 39.2
  Bottom Layer w0.3: MSDX1.9 40,46.8 41.65,45.15 R11.1 41.3,40.9 40.7,40.3 40.7,29.8 41.6,28.9 43.28,28.9 EXP2.7
SDA: Q2.2 R3.1 U4.22 | length 9.7
  Bottom Layer w0.3: U4.22 78.65,48.25 79.1,47.8 R3.1@79.1,44.53 ; R3.1@79.05,44.23 R3.1@79.195,44.375
  Bottom Layer w0.5: Q2.2 R3.1@79.05,44.23
WR-: LCD.6 U4.41 | length 51
  Top Layer w0.3: v1(61.3,61.6) 59.5,61.6 57.5,59.6 57.5,51.4 60.6,48.3 60.6,42 62.1,40.5 LCD.6
  Bottom Layer w0.3: v1@61.4,61.6 65.7,65.9 76.2,65.9 79.65,62.45 U4.41
pads on no net: B1.3 B1.4 B2.3 B2.4 LCD.26 LCD.27 LCD.28 LCD.29 MicroSD.0 MicroSD.1 MicroSD.8 MSDX1.1 MSDX1.8 MSDX2.1 MSDX2.8 U2.11 U2.12 U2.13 U2.14 U3.9 U3.12

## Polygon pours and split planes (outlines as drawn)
NetMicroSD_6 on Bottom Layer "Top Layer-No Net" (solid, remove dead copper, pour order 6): 31.5,69.5 49,69.5 49,76.5 47.5,76.5 47.5,78.1 49,78.1 49,82 31.5,82 31.5,78.1 32.9,78.1 32.9,76.5 31.5,76.5
GND on Bottom Layer "Bottom Layer-No Net" (solid, remove dead copper, pour order 9): 22,25 20.5,25.5 19.5,26.5 19,28 19,45.5 23,45.5 23,61 19,61 19,79 19.5,80.5 20.5,81.5 22,82 30,82 30,68 50.5,68 50.5,82 114,82 115.5,81.5 116.5,80.5 117,79 117,28 116.5,26.5 115.5,25.5 114,25
+3.3V on Bottom Layer "Bottom Layer-No Net" (solid, remove dead copper, pour order 7): 57,36.5 58,35.5 61.5,35.5 61.5,38 77.5,38 77.5,42 78,42.5 78,49 76,49 75,50 75,52 75.5,52.5 75.5,53 68.5,53 62.6,47.1 57,47.1
NetMicroSD_6 on Top Layer "Top Layer-No Net" (solid, remove dead copper, pour order 8): 31.5,69.5 31.5,76.5 33,76.5 33,78.1 31.5,78.1 31.5,82 49,82 49,78.2 47.5,78.2 47.5,76.5 49,76.5 49,69.5
GND on Top Layer "Bottom Layer-No Net" (solid, remove dead copper, pour order 11): 22,25 20.5,25.5 19.5,26.5 19,28 19,45.5 23,45.5 23,61 19,61 19,79 19.5,80.5 20.5,81.5 22,82 30,82 30,68 50.5,68 50.5,82 114,82 115.5,81.5 116.5,80.5 117,79 117,28 116.5,26.5 115.5,25.5 114,25

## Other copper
Bottom Layer:
  text "TFTGLCD" at 71.2,77.6 h4
  text "V2.0" at 66.4,74.7 h4

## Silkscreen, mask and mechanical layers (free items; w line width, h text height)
Bottom Overlay:
  rectangle: 35.5,35.5 36,36
  rectangle: 33.5,35.5 34,36
  rectangle: 31.5,35.5 32,36
  rectangle: 29.5,35.5 30,36
  rectangle: 27.5,35.5 28,36
  rectangle: 27.5,37 28,37.5
  rectangle: 29.5,37 30,37.5
  rectangle: 31.5,37 32,37.5
  rectangle: 33.5,37 34,37.5
  rectangle: 35.5,37 36,37.5
  lines w0.1: 19,26 19,25 20,25 ; 19,81 19,82 20,82 ; 116,25 117,25 117,26 ; 116,82 117,82 117,81
  text "B1" at 87.7,73.2 h1.3 r270
  text "B2" at 90.3,73.2 h1.3 r270
  text "B3" at 92.9,73.2 h1.3 r270
  text "B4" at 95.5,73.2 h1.3 r270
  text "B5" at 98,73.2 h1.3 r270
  text "Left" at 55.6,68.4 h1.5
  text "Right" at 55.6,63.3 h1.5
  text "DIO" at 67,63.3 h1.5 r270
  text "GND" at 69.6,63.3 h1.5 r270
  text "+3.3V" at 72.1,63.3 h1.5 r270
  text "CLK" at 74.7,63.3 h1.5 r270
  text "KILL" at 27.1,38 h1.5 r270
  text "MOSI" at 31,38 h1.5 r270
  text "SD-CS" at 33,38 h1.5 r270
  text "SCK" at 35,38 h1.5 r270
  text "SDA" at 79.7,34.8 h1.5 r270
  text "SCL" at 82.3,34.8 h1.5 r270
  text "GND" at 84.8,34.8 h1.5 r270
  text "+5V" at 77,34.7 h1.5 r270
  text "GND" at 27,31 h1.5 r270
  text "MISO" at 35,29.8 h1.5 r270
  text "SDDET" at 29,28 h1.5 r270
  text "LCD-CS" at 33,26.5 h1.5 r270
Top Solder:
  rectangle: 47.55,78.1 48.95,80
  rectangle: 31.5,78.1 32.9,80
Bottom Solder:
  rectangle: 47.55,78.1 48.95,80
  rectangle: 31.5,78.1 32.9,80
OutBoard:
  the board outline again, w0.2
